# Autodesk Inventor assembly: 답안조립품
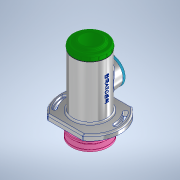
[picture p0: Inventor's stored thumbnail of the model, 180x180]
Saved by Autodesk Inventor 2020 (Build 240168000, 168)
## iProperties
Created: 2022-05
Part Number: 답안조립품
Document SubType Name: Assembly
Designer: Student
Author: Student
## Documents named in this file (21)
- C:\Users\Student\Desktop\720506V1016\답안조립품.iam
- C:\Users\Student\Desktop\720506V1016\본체.ipt
- C:\Users\Student\Desktop\720506V1016\축.ipt
- C:\Users\Student\Desktop\720506V1016\베어링 6202.ipt
- C:\Users\Student\Desktop\720506V1016\부시1.ipt
- C:\Users\Student\Desktop\720506V1016\멈춤링 15 x 1.ipt
- C:\Users\Student\Desktop\720506V1016\멈춤링 35 x 1.6.ipt
- C:\Users\Student\Desktop\720506V1016\부시2.ipt
- C:\Users\Student\Desktop\720506V1016\와셔 10 x 21.ipt
- C:\Users\Student\Desktop\720506V1016\너트 M10.ipt
- C:\Users\Student\Desktop\720506V1016\오일 실 15 x 30 x 7.ipt
- C:\Users\Student\Desktop\720506V1016\키 4 x 4.ipt
- C:\Users\Student\Desktop\720506V1016\V-벨트풀리.ipt
- C:\Users\Student\Desktop\720506V1016\와셔 4 x 16.ipt
- C:\Users\Student\Desktop\720506V1016\볼트 M4 x 10.ipt
- C:\Users\Student\Desktop\720506V1016\개스킷.ipt
- C:\Users\Student\Desktop\720506V1016\사이드 커버.ipt
- 사이드 커버.ipt
- C:\Users\Student\Desktop\720506V1016\와셔 3 x 6.ipt
- C:\Users\Student\Desktop\720506V1016\십자볼트 M3 x 10.ipt
- C:\Users\Student\Desktop\720506V1016\탑 커버.ipt
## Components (3 placed, 3 different names)
1. V-벨트풀리:1
2. ISO 4017 M4 x 10:1
3. 개스킷:1
